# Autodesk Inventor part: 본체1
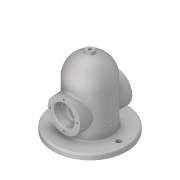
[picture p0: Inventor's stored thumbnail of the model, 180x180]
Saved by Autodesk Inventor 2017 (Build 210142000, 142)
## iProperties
Created: 2019-11
Part Number: 본체1
Material: Aluminum 6061
Document SubType Name: Modeling
Designer: 1-15-lg-1
Density: 2.7 g/cm^3
Appearance: Aluminum - Flat
Mass: 1106.12 g
Surface Area: 883.263 cm^2
Volume: 409.676 cm^3
Author: 1-15-lg-1
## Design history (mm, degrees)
sketch "Sketch2"
  geometry: C1 r 70 at (0, 0); 1 further point
  constraints: 1 centre point, 1 coincident
  dimensions: "d0" = 140 diameter of C1
extrude "Extrusion1" new body sketch "Sketch2" distance "d1" = 10; taper "d2" = 0 deg
sketch "Sketch3"
  geometry: L1 (10, -70)-(10, 70) reference; L2 (0, 0)-(90, 0); L3 (4.905, 40)-(4.905, -40); L4 (10, 40)-(90, 40); L5 (10, -40)-(90, -40); L6 (10, 0)-(130, 0); A1 r 40 centre (90, 0) between (90, -40) and (90, 40)
  constraints: 10 end point, 3 horizontal, 3 point on circle, 3 point on line, 1 centre point, 1 coincident, 1 midpoint, 1 vertical
  dimensions: "d4" = 80 diameter of A1; "d5" = 90 distance of L2.start L2.end; "d6" = 80 distance of L3.start L3.end; "d7" = 40 distance from line of L3.end L2
revolve "Revolution1" sketch "Sketch3" stored, may be unused: angle "d8" = 90 deg
sketch "Sketch4"
  geometry: L1 (0, 0)-(0, 50); L2 (-70, 0)-(70, 0) reference; C1 r 31 at (0, 50)
  constraints: 2 end point, 1 centre point, 1 coincident, 1 perpendicular
  dimensions: "d9" = 50 distance of L1.start L1.end; "d10" = 62 diameter of C1
extrude "Extrusion2" join sketch "Sketch4" stored distance "d11" = 100; taper "d12" = 0 deg
sketch "Sketch5"
  geometry: C1 r 31 at (0, 0) reference; C2 r 20 at (0, 0); 1 further point
  constraints: 1 centre point, 1 coincident
  dimensions: "d13" = 40 diameter of C2
extrude "Extrusion3" cut sketch "Sketch5" distance "d14" = 15; taper "d15" = 0 deg
mirror "Mirror1"
sketch "Sketch6"
  geometry: C1 r 20 at (0, 0) reference; C2 r 16.5 at (0, 0); 1 further point
  constraints: 1 centre point, 1 coincident
  dimensions: "d16" = 33 diameter of C2
extrude "Extrusion4" cut sketch "Sketch6" stored distance "d17" = 15; taper "d18" = 0 deg
sketch "Sketch8"
  geometry: L1 (0, 0)-(90, 0); L2 (0, 0)-(0, -30); L3 (0, 70)-(0, -70) reference; L4 (0, -30)-(90, -30); L5 (0, 0)-(120, 0); A1 r 30 centre (90, 0) between (90, -30) and (120, 0)
  constraints: 8 end point, 3 horizontal, 2 point on circle, 1 centre point, 1 coincident, 1 point on line
  dimensions: "d19" = 90 distance of L1.start L1.end; "d20" = 60 diameter of A1; "d21" = 30 distance of L1.start L2.end
revolve "Revolution2" sketch "Sketch8" stored, may be unused: angle "d22" = 90 deg
sketch "Sketch9" dims "d23" = 110
  geometry: L1 (0, 0)-(55, 0); C1 r 70 at (0, 0) reference; C2 r 4.5 at (55, 0)
  constraints: 2 coincident, 2 end point, 1 centre point, 1 horizontal, 1 horizontal alignment, 2 other
  dimensions: "d24" = 9 diameter of C2
extrude "Extrusion5" cut sketch "Sketch9" stored distance "d25" = 10; taper "d26" = 0 deg
mirror "Mirror2"
workplane "Work Plane1"
sketch "Sketch10"
  geometry: C1 r 7.5 at (0, 0); 1 further point
  constraints: 1 centre point, 1 coincident
  dimensions: "d28" = 15 diameter of C1
extrude "Extrusion6" join sketch "Sketch10" stored distance "d29" = 10; taper "d30" = 0 deg
sketch "Sketch11"
  geometry: C1 r 7.5 at (0, 0) reference; 1 further point
  constraints: 1 coincident
hole "Hole1" sketch "Sketch11" at (0, 0) diameter "d31" = 5.188; stored, may be unused: countersink angle "d35" = 90 deg, drill point angle "d37" = 118 deg; dims "d32" = 12, "d33" = 4, "d34" = 2, "d36" = 16
sketch "Sketch12" dims "d38" = 52
  geometry: L1 (0, 0)-(0, 26); C1 r 31 at (0, 0) reference; 2 further points
  constraints: 2 coincident, 2 end point, 1 vertical, 1 vertical alignment, 2 other
hole "Hole2" sketch "Sketch12" at (0, 26) diameter "d39" = 3.242; stored, may be unused: countersink angle "d43" = 90 deg, drill point angle "d45" = 118 deg; dims "d40" = 8, "d41" = 4, "d42" = 2, "d44" = 10
pattern_circular "Circular Pattern1" dims angle "d47" = 360 deg
mirror "Mirror3"
workplane "Work Plane2"
sketch "Sketch13"
  geometry: L1 (76.553, 15.337)-(76.553, -15.337); L2 (76.553, -15.337)-(23.447, -15.337); L3 (23.447, -15.337)-(23.447, 15.337); L4 (23.447, 15.337)-(76.553, 15.337); L5 (76.553, 0)-(23.447, 0); L6 (50, 15.337)-(50, -15.337); L7 (135, 7.5)-(135, -7.5) reference; L8 (135, 0)-(0, 0); L9 (0, 70)-(0, -70) reference; 1 further point
  constraints: 6 end point, 6 midpoint, 1 horizontal, 2 other
emboss "Emboss1" sketch "Sketch13" dims "d53" = 0.5, "d54" = 0
fillet "Fillet1" dims "d55" = 0.3
chamfer "Chamfer1" distance "d56" = 1; stored, may be unused: second distance "d57" = 2, angle "d58" = 45 deg
fillet "Fillet2" dims "d59" = 3
body "Solid1"
other parameters: "d27" = 135
